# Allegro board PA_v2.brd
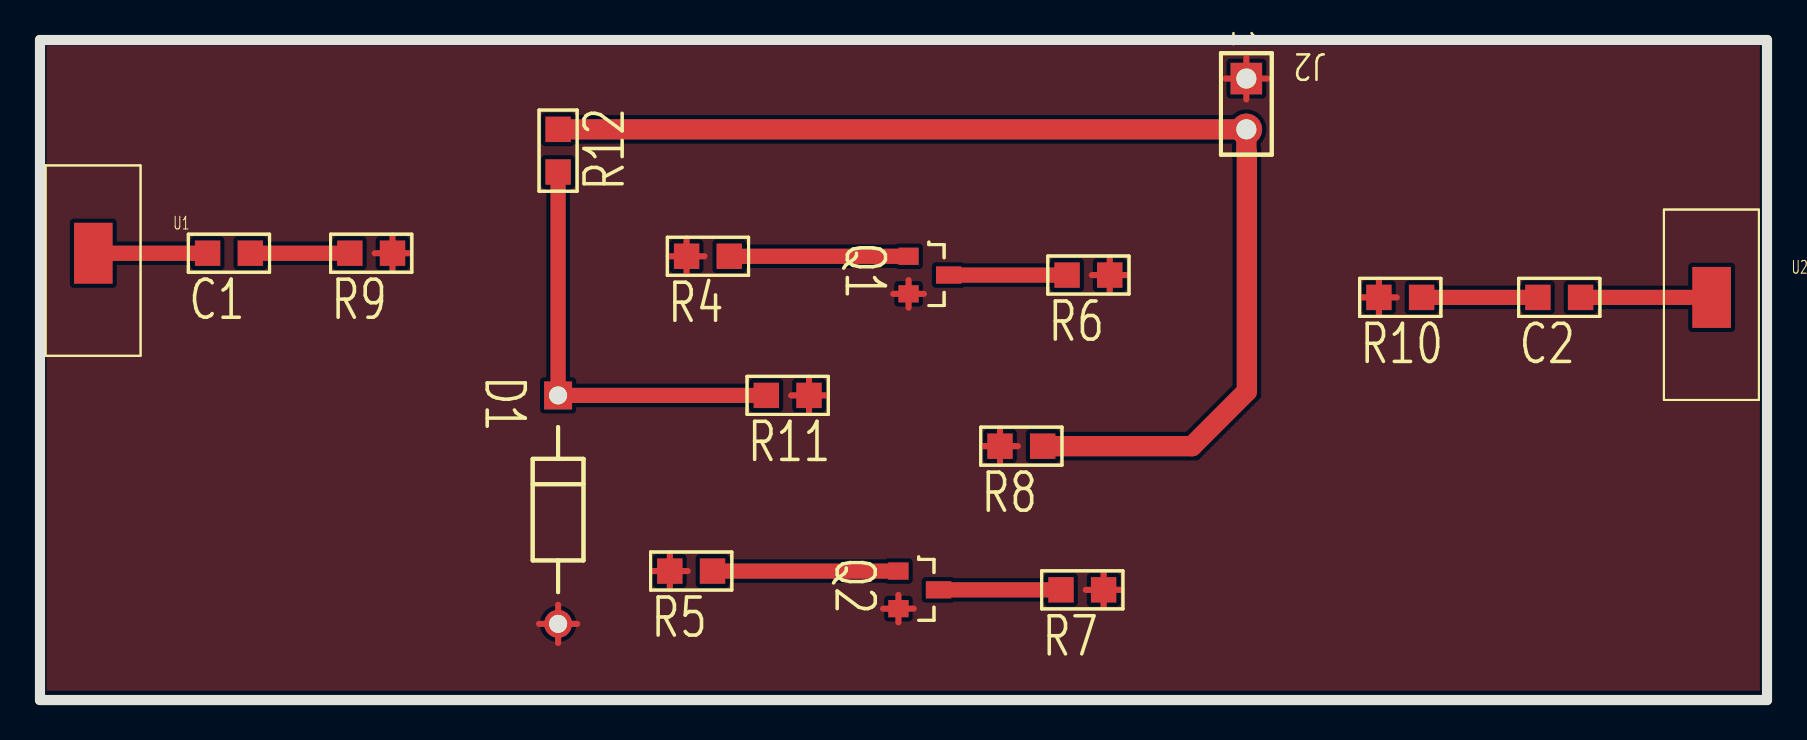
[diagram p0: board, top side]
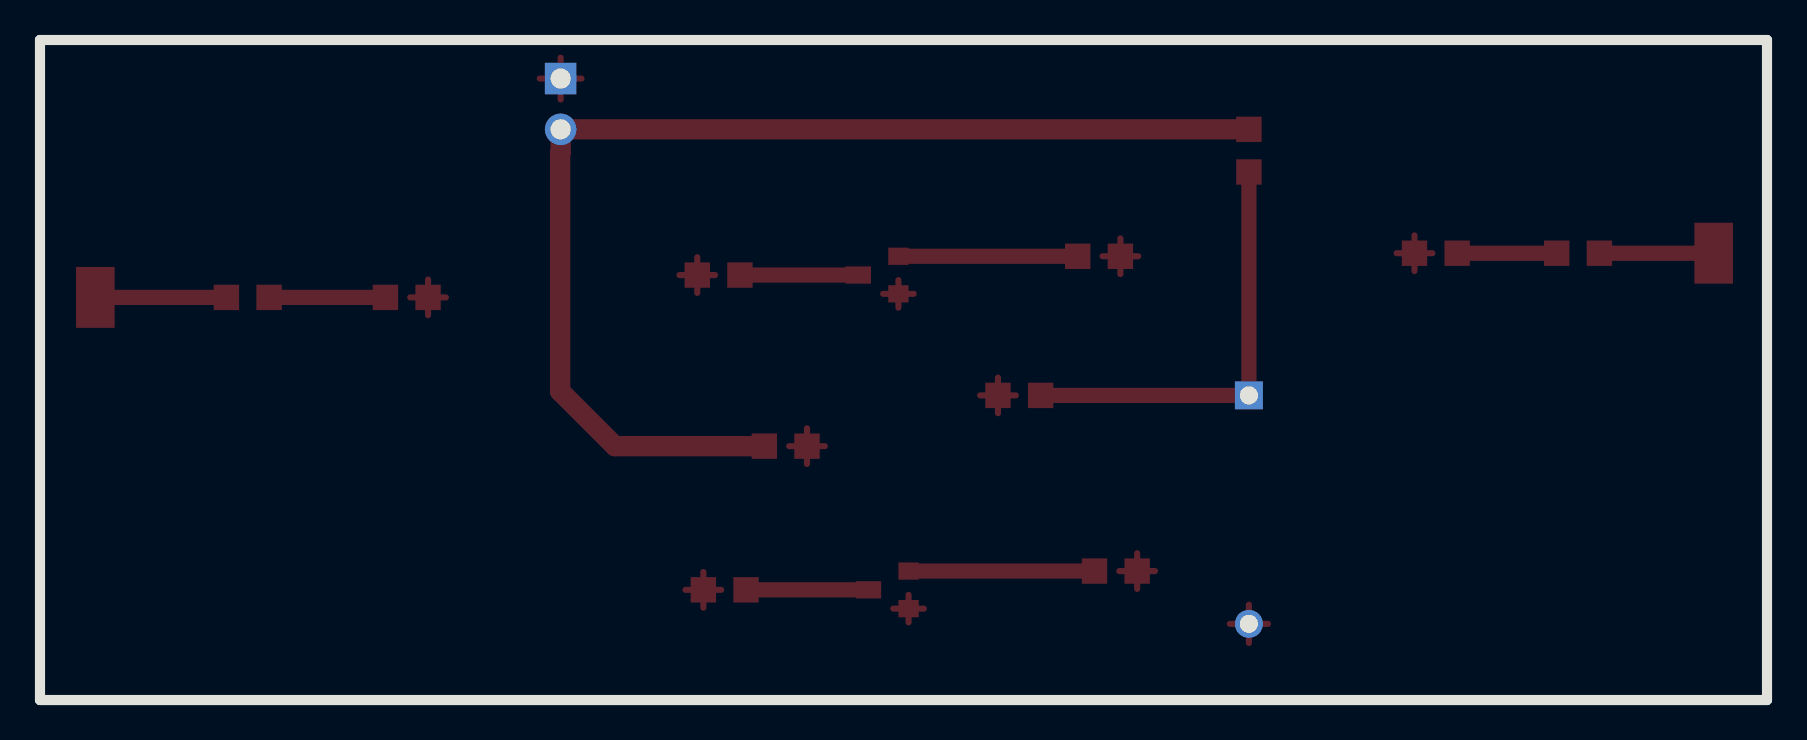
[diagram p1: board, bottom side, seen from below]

Outline 86.36 x 33.02 mm; copper layers: TOP, BOTTOM. Coordinates in mm from the lower left corner of the outline.
Outline path: 0,33.02 0,0 86.36,0 86.36,33.02 0,33.02

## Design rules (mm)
constraint set DEFAULT: min track width 0.305

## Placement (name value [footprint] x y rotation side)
C1  C NP  [SMC0805]  8.38 22.35 0 top
C2  C NP  [SMC0805]  74.9 20.14 0 top
D1  1N4500  [DAX1DO35]  25.91 15.24 270 top
J2  2Pin Header  [BCON_2X1V_100S_1SQ_42D]  60.33 31.09 270 top
Q1  Q2N3904  [SMSOT23BEC]  43.43 20.32 270 top
Q2  Q2N3904  [SMSOT23BEC]  42.93 4.57 270 top
R4  R small  [SMC0805]  32.33 22.2 0 top
R5  R small  [SMC0805]  31.5 6.45 0 top
R6  R small  [SMC0805]  51.36 21.26 0 top
R7  R small  [SMC0805]  51.05 5.51 0 top
R8  R small  [SMC0805]  48.01 12.7 0 top
R9  R small  [SMC0805]  15.49 22.35 0 top
R10  R small  [SMC0805]  66.95 20.14 0 top
R11  R small  [SMC0805]  36.32 15.24 0 top
R12  1k  [SMR0805]  25.91 26.42 90 top
U1  SMA_connector  [SMACONNECTOR]  0.28 17.22 0 top
U2  SMA_connector  [SMACONNECTOR]  81.2 15.01 0 top

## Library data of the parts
C1 C2 = C NP
D1 = 1N4500_0
J2 = 2Pin Header
Q1 Q2 = Q2N3904_2
R4-R11 = R small
R12 = R
U1 U2 = SMA_connector

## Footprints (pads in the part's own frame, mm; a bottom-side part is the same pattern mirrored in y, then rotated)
BCON_2X1V_100S_1SQ_42D
  rect 1.575x1.575 hole 1.001: 1(0,0)
  round 1.575 hole 1.001: 2(2.54,0)
DAX1DO35
  rect 1.397x1.397 hole 0.899: 1(0,0)
  round 1.397 hole 0.899: 2(11.43,0)
SMACONNECTOR
  rect 1.93x3.048 smd: 1(2.388,5.131)
SMC0805
  rect 1.27x1.27 smd: 1(0,0) 2(2.134,0)
SMR0805
  rect 1.27x1.27 smd: 1(0,0) 2(2.134,0)
SMSOT23BEC
  rect 0.864x1.016 smd: B(-1.88,0) E(0,0)
  rect 0.864x1.27 smd: C(-0.94,2.007)

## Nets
0: D1.2(K) J2.1 Q1.E Q2.E R4.1 R5.1 R6.2(B) R7.2(B) R8.1 R9.2(B) R10.1 R11.2(B)
N02016: J2.2 R8.2(B) R12.2(B)
N02118: D1.1 R11.1 R12.1
N02198: Q1.C R6.1
N02228: C1.2(B) R9.1
N02288: C2.1 R10.2(B)
N02428: Q2.B R5.2(B)
N02440: Q2.C R7.1
N021060: C1.1 U1.1(VIN)
N022200: C2.2(B) U2.1(VIN)
N023001: Q1.B R4.2(B)

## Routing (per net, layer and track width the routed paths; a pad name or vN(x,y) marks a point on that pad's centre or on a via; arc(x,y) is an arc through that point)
0: length 42.3
  TOP w0.305: Q1.E 43.43,21.01 ; Q1.E 43.43,19.63 ; Q1.E 44.2,20.32 ; Q1.E 42.67,20.32 ; 37.56,15.24 R11.2 ; R11.2 38.46,14.35 ; R11.2 39.35,15.24 ; R11.2 38.46,16.13 ; D1.2 25.91,4.77 ; D1.2 26.86,3.81 ; D1.2 24.95,3.81 ; D1.2 25.91,2.85 ; 31.44,22.2 R4.1 ; R4.1 33.23,22.2 ; R4.1 32.33,23.09 ; R4.1 32.33,21.31 ; 30.6,6.45 R5.1 ; R5.1 31.5,5.56 ; R5.1 32.39,6.45 ; R5.1 31.5,7.34 ; R6.2 54.38,21.26 ; R6.2 53.49,22.15 ; R6.2 53.49,20.37 ; R6.2 52.6,21.26 ; R7.2 54.08,5.51 ; R7.2 53.19,4.62 ; R7.2 53.19,6.4 ; R7.2 52.3,5.51 ; Q2.E 43.69,4.57 ; Q2.E 42.93,5.26 ; Q2.E 42.93,3.88 ; Q2.E 42.16,4.57 ; 59.28,31.09 J2.1 ; J2.1 61.37,31.09 ; J2.1 60.33,32.13 ; J2.1 60.33,30.05 ; R8.1 48.9,12.7 ; R8.1 47.11,12.7 ; R8.1 48.01,11.81 ; R8.1 48.01,13.59 ; 17.63,21.46 R9.2 ; R9.2 17.63,23.24 ; R9.2 16.74,22.35 ; R9.2 18.52,22.35 ; R10.1 66.95,21.03 ; R10.1 67.85,20.14 ; R10.1 66.06,20.14 ; R10.1 66.95,19.25
N02016: length 58.9
  TOP w1.016: R12.2 J2.2 60.33,27.41 60.35,27.38 60.35,15.44 57.61,12.7 R8.2
N02118: length 21.6
  TOP w0.762: R12.1 D1.1 R11.1
N02198: length 5.9
  TOP w0.762: R6.1 Q1.C
N02228: length 5
  TOP w0.762: C1.2 R9.1
N02288: length 5.8
  TOP w0.762: R10.2 C2.1
N02428: length 9.3
  TOP w0.762: R5.2 Q2.B
N02440: length 6.1
  TOP w0.762: Q2.C R7.1
N021060: length 5.7
  TOP w0.762: U1.1 C1.1
N022200: length 6.6
  TOP w0.762: C2.2 U2.1
N023001: length 9
  TOP w0.762: Q1.B R4.2

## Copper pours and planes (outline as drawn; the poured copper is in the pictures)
0 on TOP: 0.33,32.74 0.33,0.46 86,0.46 86,32.74

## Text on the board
NCLEGEND-1-2: FIGURE | SIZE | 35.4 | 39.4 | DRILL CHART: TOP to BOTTOM | ALL UNITS ARE IN MILS | PLATED | QTY | 2
